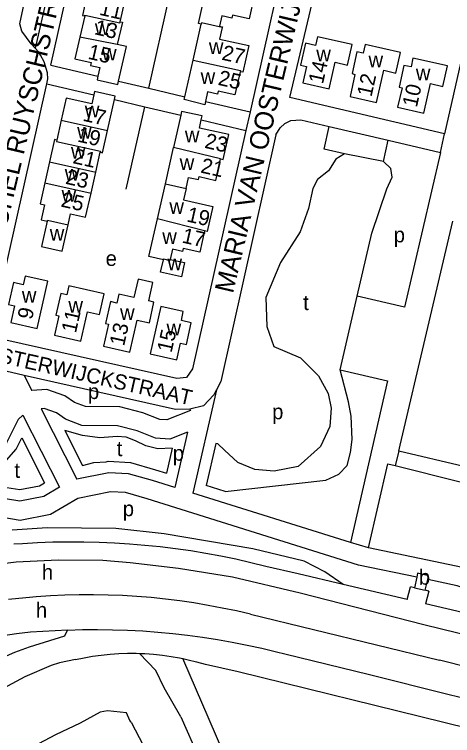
# Model space of a CAD drawing. Extents: x 161141 to 163125, y 381621 to 383200.
# Drawn here: x 162701.6 to 162817.4, y 382505.7 to 382696 of the extents above; entities that cross this region are included whole.
import ezdxf

# ---------------------------------------------------------------- set-up
doc = ezdxf.new("R2010")
doc.units = 0
for name, color, linetype in [('BLT_Basislijn', 7, 'Continuous'), ('BLT_Bebouwing', 7, 'Continuous'), ('BLT_Centroide', 7, 'Continuous'), ('BLT_Huisnummer', 7, 'Continuous'), ('BLT_Huisnummer_ tussenligend', 7, 'Continuous'), ('BLT_Onderverdeling_panden', 7, 'Continuous'), ('BLT_Straatnaam', 7, 'Continuous'), ('BLT_Straatnaam_verkleind', 7, 'Continuous'), ('BLT_Vlakafsluiter', 7, 'Continuous')]:
    doc.layers.add(name, color=color, linetype=linetype)

msp = doc.modelspace()

# ---------------------------------------------------------------- linework, layer by layer
at = {"layer": 'BLT_Basislijn'}
for p, q in [((162835.43, 382754.42), (162815.29, 382664.48)), ((162718.61, 382738.28), (162707.12, 382687.12)), ((162774.36, 382674.08), (162785.51, 382721.41)), ((162737.14, 382676.56), (162745.62, 382714.36)), ((162711.23, 382682.63), (162723.66, 382679.72)), ((162710.14, 382677.75), (162710.43, 382679.04)), ((162710.14, 382677.75), (162722.56, 382674.84)), ((162729.12, 382678.44), (162737.14, 382676.56)), ((162737.14, 382676.56), (162746.66, 382674.33)), ((162728.04, 382673.56), (162736.05, 382671.68)), ((162752.1, 382673.06), (162763.86, 382670.3)), ((162815.29, 382664.48), (162774.36, 382674.08)), ((162731.16, 382649.91), (162736.05, 382671.68)), ((162736.05, 382671.68), (162745.55, 382669.46)), ((162763.86, 382670.3), (162762.77, 382665.42)), ((162750.98, 382668.19), (162762.77, 382665.42)), ((162784.81, 382666.49), (162800.4, 382662.84)), ((162814.18, 382659.61), (162815.29, 382664.48)), ((162799.12, 382657.2), (162800.4, 382662.84)), ((162800.4, 382662.84), (162814.18, 382659.61)), ((162799.12, 382657.2), (162788.83, 382659.27)), ((162787.69, 382602.21), (162792.21, 382621.65)), ((162704.17, 382600.76), (162697.84, 382602.18)), ((162704.17, 382600.76), (162706.18, 382596.79)), ((162754.98, 382596.91), (162748.77, 382569.63)), ((162708.64, 382591.92), (162718.08, 382573.32)), ((162703.87, 382590.29), (162713.53, 382571.23)), ((162714.89, 382586.24), (162719.59, 382576.97)), ((162747.32, 382585.78), (162743.99, 382571.13)), ((162703.55, 382584.28), (162709.57, 382572.39)), ((162754.84, 382582.77), (162752.31, 382571.67)), ((162743.28, 382581.56), (162741.78, 382574.96)), ((162803.15, 382580.79), (162802.26, 382576.98)), ((162795.18, 382555.25), (162800.31, 382577.44)), ((162800.31, 382577.44), (162802.26, 382576.98)), ((162802.26, 382576.98), (162819.43, 382572.68)), ((162757.27, 382570.11), (162752.31, 382571.67)), ((162790.37, 382556.61), (162748.77, 382569.63)), ((162776.57, 382548.34), (162768.04, 382550.34)), ((162805.37, 382541.57), (162788.49, 382545.54)), ((162805.37, 382541.57), (162806.26, 382544.94)), ((162807.3, 382544.69), (162806.26, 382544.94)), ((162811.09, 382543.81), (162810.17, 382544.02)), ((162811.09, 382543.81), (162810.23, 382540.43)), ((162821.55, 382537.78), (162810.23, 382540.43)), ((162763.95, 382537.7), (162813.94, 382525.55)), ((162760.71, 382522.48), (162752.12, 382524.47)), ((162881.67, 382508.9), (162813.94, 382525.55)), ((162816.16, 382516.59), (162851.44, 382508)), ((162732.47, 382509.17), (162740.29, 382494.42))]:
    msp.add_line(p, q, dxfattribs=at)
for points in [[(162711.23, 382682.63), (162722.71, 382733.71), (162724.17, 382735.99), (162726.65, 382736.47)], [(162726.65, 382736.47), (162772.95, 382726.08), (162775.02, 382724.6), (162775.44, 382721.95), (162763.86, 382670.3)], [(162707.12, 382687.12), (162706.01, 382688.31), (162703.53, 382691.59), (162703.02, 382693.58), (162712.03, 382735.63)], [(162708.5, 382685.25), (162707.97, 382686.2), (162707.12, 382687.12)], [(162710.43, 382679.04), (162710.31, 382680.65), (162709.43, 382683.57), (162708.5, 382685.25)], [(162762.77, 382665.42), (162748.66, 382602.48), (162747.05, 382600.23), (162744.53, 382599.9), (162698.59, 382610.21), (162696.32, 382611.84), (162695.88, 382614.28), (162710.14, 382677.75)], [(162770.7, 382664.23), (162771.81, 382666.12), (162773.05, 382667.29), (162774.66, 382668.03), (162777.29, 382668.26), (162784.81, 382666.49)], [(162788.83, 382659.27), (162783.47, 382660.46), (162784.81, 382666.49)], [(162770.7, 382664.23), (162756.11, 382599.15), (162754.98, 382596.91)], [(162788.83, 382659.27), (162786.56, 382657.79), (162784.58, 382654.72), (162781.68, 382652.5), (162780.42, 382650.12), (162779.29, 382644.83), (162777.08, 382638.68), (162771.89, 382630.57), (162768.05, 382621.34), (162768.34, 382613.62), (162770.12, 382608.38), (162777.24, 382605.36), (162781.98, 382600.62), (162784.54, 382596.01), (162785.3, 382592.12), (162784.94, 382587.25), (162782.51, 382581.94), (162776.55, 382576.71), (162770.25, 382575.44), (162765.11, 382575.9), (162760.67, 382577.8), (162757.11, 382581.05), (162755.32, 382582.66), (162754.84, 382582.77)], [(162814.18, 382659.61), (162804.71, 382618.75), (162792.21, 382621.65)], [(162792.21, 382621.65), (162796.07, 382638.32), (162799.99, 382650.02), (162801.39, 382653.06), (162801.1, 382655.41), (162799.12, 382657.2)], [(162747.99, 382591.83), (162744.16, 382591.79), (162704.17, 382600.76)], [(162757.27, 382570.11), (162783.9, 382573.09), (162787.33, 382574.64), (162789.53, 382576.98), (162790.44, 382580.37), (162790.84, 382583.86), (162790.56, 382589.96), (162789.87, 382593.78), (162787.69, 382602.21)], [(162787.69, 382602.21), (162800.23, 382599.29), (162790.37, 382556.61)], [(162747.99, 382591.83), (162748.12, 382591.49), (162741.89, 382588.99), (162740, 382589.1), (162735.58, 382590.89), (162729.49, 382592.46), (162720.37, 382592.52), (162717.47, 382593.64), (162714.95, 382595.36), (162710.16, 382597.02), (162706.18, 382596.79)], [(162754.98, 382596.91), (162754.32, 382595.59), (162751.53, 382592.74), (162747.99, 382591.83)], [(162747.32, 382585.78), (162742.71, 382583.94), (162738.89, 382584.16), (162734.01, 382586.13), (162728.84, 382587.46), (162719.42, 382587.53), (162715.13, 382589.19), (162712.69, 382590.85), (162709.46, 382591.97), (162708.64, 382591.92)], [(162703.87, 382590.29), (162702.59, 382589.07), (162699.54, 382582.95), (162697.01, 382580.08), (162693.75, 382578.47), (162689.15, 382577.94), (162671.68, 382581.55), (162661.08, 382583.27), (162655, 382582), (162643.58, 382576.04), (162635.25, 382575.98)], [(162743.28, 382581.56), (162739.52, 382581.39), (162736.37, 382582.15), (162733.63, 382583.45), (162731.14, 382584.41), (162728.72, 382584.64), (162724.15, 382584.28), (162719.59, 382584.86), (162714.89, 382586.24)], [(162692.86, 382575.35), (162694.61, 382575.55), (162698.87, 382577.65), (162702.05, 382581.26), (162703.55, 382584.28)], [(162719.59, 382576.97), (162722.63, 382577.78), (162725.81, 382577.96)], [(162725.81, 382577.96), (162726.38, 382578.07), (162732.25, 382577.74), (162738.93, 382575.86), (162741.78, 382574.96)], [(162743.99, 382571.13), (162738.07, 382572.98), (162731.75, 382574.76), (162726.59, 382575.06), (162718.08, 382573.32)], [(162697.23, 382571.54), (162703.02, 382570.59), (162708.26, 382571.62), (162709.57, 382572.39)], [(162713.53, 382571.23), (162709.34, 382568.78), (162703.06, 382567.54), (162695.34, 382568.81), (162690.28, 382568.97), (162676.08, 382565.57), (162670.15, 382562.62), (162664.7, 382561.09), (162659.13, 382560.99), (162654.86, 382562.05), (162648.9, 382562.56), (162643.26, 382561.66)], [(162807.9, 382547.46), (162792.55, 382550.69), (162736.65, 382568.19), (162730.92, 382569.8), (162726.96, 382570.03), (162718.36, 382568.27), (162711.14, 382564.04), (162703.14, 382562.46), (162694.85, 382563.83), (162690.79, 382563.96), (162677.8, 382560.84), (162671.95, 382557.93), (162665.43, 382556.1), (162658.56, 382555.98), (162654.04, 382557.1), (162649.08, 382557.53), (162645.86, 382557.01)], [(162788.49, 382545.54), (162783.64, 382548.91), (162778.14, 382551.71), (162764.57, 382554.97), (162741.18, 382558.95), (162728.39, 382560.31), (162710.28, 382560.55), (162701.04, 382559.91)], [(162768.04, 382550.34), (162764.1, 382551.31), (162760.14, 382552.2), (162756.17, 382553.01), (162752.18, 382553.74), (162748.18, 382554.4), (162744.16, 382554.97), (162740.14, 382555.47), (162736.11, 382555.88), (162732.06, 382556.22), (162728.02, 382556.48), (162723.96, 382556.65), (162719.91, 382556.75), (162715.86, 382556.76), (162711.8, 382556.7), (162707.75, 382556.56), (162703.7, 382556.33), (162701.42, 382556.17)], [(162873.97, 382530.99), (162819.97, 382550.04), (162795.18, 382555.25)], [(162569.6, 382521.35), (162584.37, 382523.33), (162593.88, 382525.6), (162600, 382527.33), (162655.99, 382543.26), (162670.43, 382546.76), (162685.89, 382549.55), (162702.06, 382551.54), (162713.15, 382552.1), (162724.94, 382551.95), (162732.15, 382551.34), (162744.93, 382549.87), (162759.21, 382547.56), (162777.1, 382543.36)], [(162872.83, 382526.09), (162818.61, 382545.21), (162810.81, 382546.85)], [(162763.95, 382537.7), (162760.25, 382538.56), (162756.53, 382539.34), (162752.79, 382540.05), (162749.04, 382540.67), (162745.28, 382541.22), (162741.51, 382541.69), (162737.73, 382542.08), (162733.94, 382542.39), (162730.14, 382542.62), (162726.34, 382542.77), (162722.54, 382542.84), (162718.74, 382542.83), (162714.94, 382542.74), (162711.14, 382542.57), (162707.35, 382542.32), (162706.45, 382542.24), (162700.03, 382541.58)], [(162777.1, 382543.36), (162809.81, 382535), (162973.35, 382494.97)], [(162635.09, 382492.15), (162665.21, 382508.92), (162681.25, 382517.73), (162685.54, 382519.91), (162688.83, 382522.06), (162701.71, 382527.67), (162705.61, 382529.13), (162714.9, 382532), (162715.61, 382533.53)], [(162715.61, 382533.53), (162705.86, 382532.98), (162702.2, 382532.57), (162688.42, 382530.52), (162682.16, 382529.39), (162667.63, 382525.88), (162662.54, 382524.47), (162655.66, 382522.39), (162644.49, 382518.49)], [(162715.61, 382533.53), (162719.59, 382533.64), (162723.57, 382533.67), (162727.55, 382533.62), (162731.52, 382533.49), (162735.5, 382533.28), (162739.46, 382532.99), (162743.43, 382532.62), (162747.38, 382532.17), (162751.33, 382531.64), (162755.26, 382531.04), (162759.18, 382530.35), (162763.08, 382529.58), (162766.97, 382528.74), (162770.84, 382527.82), (162773.1, 382527.24)], [(162717.74, 382525.73), (162720, 382526.21), (162722.28, 382526.6), (162724.57, 382526.92), (162726.87, 382527.16), (162729.17, 382527.31), (162731.48, 382527.39), (162733.79, 382527.39), (162734.62, 382527.36)], [(162734.62, 382527.36), (162736.1, 382527.3), (162738.4, 382527.14), (162740.7, 382526.9), (162742.99, 382526.58), (162745.26, 382526.18), (162746.13, 382525.99)], [(162745.62, 382510.59), (162741.15, 382518.26), (162738.98, 382522.83), (162734.62, 382527.36)], [(162773.1, 382527.24), (162795.46, 382521.83), (162816.16, 382516.59)], [(162717.74, 382525.73), (162713.53, 382524.85), (162711.3, 382524.13), (162704.33, 382521.18), (162697.44, 382517.47), (162696.59, 382516.78), (162651.61, 382490.8), (162648.85, 382489.01), (162625.07, 382475.48), (162622.04, 382472.42), (162620.44, 382469.49), (162619.11, 382464.04), (162619.69, 382459.37), (162620.18, 382458.53)], [(162769.9, 382470.76), (162768.63, 382473.86), (162746.13, 382525.99)], [(162746.13, 382525.99), (162747.52, 382525.7), (162749.76, 382525.14), (162751.99, 382524.51), (162752.12, 382524.47)], [(162915.76, 382484.32), (162815.12, 382509.09), (162760.71, 382522.48)], [(162732.47, 382509.17), (162732.08, 382509.61), (162731.19, 382511.7), (162726.24, 382512.22), (162724.24, 382511.84), (162718.98, 382508.96), (162712.44, 382505.83), (162698.84, 382498.61), (162698.08, 382498.37), (162691.49, 382494.7), (162628.15, 382461.41), (162628.26, 382460.6), (162629.1, 382458.51), (162642.19, 382433.33), (162648.99, 382420.26)], [(162745.62, 382510.59), (162750.26, 382500.06), (162766.91, 382460.44)]]:
    msp.add_lwpolyline(points, dxfattribs=at)
at = {"layer": 'BLT_Bebouwing'}
for p, q in [((162729.54, 382694.1), (162730.76, 382699.43)), ((162720.17, 382695.66), (162718.91, 382690.07)), ((162748.83, 382684), (162750.95, 382693.49)), ((162746.66, 382674.33), (162748.83, 382684)), ((162726.19, 382665.38), (162728.04, 382673.56)), ((162745.55, 382669.46), (162743.64, 382660.95)), ((162713.98, 382668.11), (162712.81, 382662.88)), ((162723.1, 382654.39), (162724.29, 382659.67)), ((162741.49, 382651.36), (162743.64, 382660.95)), ((162710.9, 382657.12), (162709.66, 382651.55)), ((162721.85, 382648.82), (162723.1, 382654.39)), ((162739.4, 382642.05), (162741.49, 382651.36)), ((162710.26, 382641.5), (162708.77, 382634.76)), ((162803.52, 382582.36), (162817.43, 382641.46)), ((162820.39, 382576.73), (162803.15, 382580.79)), ((162807.9, 382547.46), (162807.3, 382544.69)), ((162810.17, 382544.02), (162810.81, 382546.85))]:
    msp.add_line(p, q, dxfattribs=at)
for points in [[(162750.95, 382693.49), (162750.21, 382693.66), (162752.62, 382704.34), (162754.89, 382703.54)], [(162720.94, 382701.88), (162719.58, 382695.79), (162720.17, 382695.66)], [(162764.99, 382700.99), (162763.61, 382694.85), (162759.21, 382695.83), (162759.04, 382695.04), (162756.4, 382695.63), (162755.8, 382692.93), (162756.58, 382692.76), (162756.53, 382692.56)], [(162729.54, 382694.1), (162730.13, 382693.97), (162728.79, 382688.11)], [(162756.53, 382692.56), (162755.84, 382689.53), (162763.57, 382687.82), (162761.99, 382680.77), (162761.26, 382680.93)], [(162718.91, 382690.07), (162717.61, 382684.29), (162721.86, 382683.34), (162721.68, 382682.56), (162724.17, 382682), (162723.66, 382679.72)], [(162729.12, 382678.44), (162731.19, 382687.56), (162728.79, 382688.11)], [(162761.26, 382680.93), (162759.86, 382674.79), (162755.48, 382675.78), (162755.3, 382675), (162752.67, 382675.59), (162752.1, 382673.06)], [(162723.66, 382679.72), (162723.45, 382678.77), (162728.92, 382677.53), (162729.12, 382678.44)], [(162728.04, 382673.56), (162728.24, 382674.46), (162722.75, 382675.68), (162722.56, 382674.84)], [(162722.56, 382674.84), (162722.03, 382672.48), (162715.3, 382673.98), (162713.98, 382668.11)], [(162752.1, 382673.06), (162751.9, 382672.18), (162746.5, 382673.6), (162746.66, 382674.33)], [(162750.98, 382668.19), (162751.23, 382669.29), (162745.78, 382670.46), (162745.55, 382669.46)], [(162756.09, 382657.9), (162756.81, 382657.72), (162758.29, 382664.31), (162750.51, 382666.05), (162750.98, 382668.19)], [(162724.29, 382659.67), (162724.87, 382659.54), (162726.19, 382665.38)], [(162712.81, 382662.88), (162712.22, 382662.99), (162710.9, 382657.12)], [(162746.96, 382650.1), (162747.62, 382653.03), (162750.24, 382652.44), (162750.42, 382653.22), (162754.81, 382652.24), (162756.09, 382657.9)], [(162709.66, 382651.55), (162708.43, 382646.07), (162709.58, 382645.81), (162708.69, 382641.86), (162710.26, 382641.5)], [(162715.81, 382640.49), (162716.47, 382643.44), (162720.43, 382642.55), (162721.85, 382648.82)], [(162746.96, 382650.1), (162746.28, 382647.13), (162754.05, 382645.37), (162752.56, 382638.78), (162751.84, 382638.95)], [(162740.99, 382631.23), (162737.16, 382632.1), (162739.4, 382642.05)], [(162708.77, 382634.76), (162714.24, 382633.53), (162715.81, 382640.49)], [(162751.84, 382638.95), (162750.56, 382633.29), (162746.16, 382634.26), (162745.99, 382633.49), (162743.35, 382634.09), (162742.74, 382631.39)], [(162742.74, 382631.39), (162746.56, 382630.53), (162745.72, 382626.78), (162740.25, 382628), (162740.99, 382631.23)], [(162738.48, 382620.11), (162737.1, 382620.42), (162738.19, 382625.29), (162734.29, 382626.17), (162733.2, 382621.29), (162729.17, 382622.19), (162728.65, 382619.86), (162727, 382620.22), (162725.7, 382614.47), (162726.48, 382614.28), (162725.18, 382608.44), (162732.13, 382606.88), (162734.04, 382615.37), (162737.32, 382614.63), (162738.48, 382620.11)], [(162803.15, 382580.79), (162803.52, 382582.36)], [(162810.81, 382546.85), (162811.04, 382547.88), (162808.13, 382548.55), (162807.9, 382547.46)], [(162807.3, 382544.69), (162810.17, 382544.02)]]:
    msp.add_lwpolyline(points, dxfattribs=at)
for points in [[(162781.69, 382690.17), (162781.17, 382687.84), (162778.55, 382688.42), (162777.24, 382682.69), (162778.8, 382682.33), (162777.81, 382677.95), (162784.78, 382676.38), (162786.4, 382683.41), (162789.62, 382682.67), (162790.84, 382688.12)], [(162803.6, 382686.03), (162794.29, 382688.11), (162793.77, 382685.8), (162792.12, 382686.16), (162790.84, 382680.41), (162791.6, 382680.22), (162790.3, 382674.37), (162797.26, 382672.8), (162799.18, 382681.29), (162802.38, 382680.56)], [(162804.54, 382682.59), (162803.23, 382676.86), (162804.03, 382676.68), (162802.87, 382671.57), (162809.83, 382670.01), (162811.59, 382677.77), (162814.79, 382677.04), (162816.01, 382682.46), (162806.92, 382684.5), (162806.41, 382682.18)], [(162710.43, 382625.63), (162704.48, 382626.98), (162703.96, 382624.66), (162701.34, 382625.24), (162700.07, 382619.47), (162701.63, 382619.12), (162700.64, 382614.73), (162707.61, 382613.17)], [(162725.35, 382622.28), (162716.02, 382624.38), (162715.49, 382622.04), (162713.85, 382622.41), (162712.55, 382616.66), (162713.33, 382616.48), (162712.22, 382611.35), (162719.16, 382609.8), (162720.89, 382617.51), (162724.12, 382616.83)], [(162746.24, 382617.6), (162740.34, 382618.91), (162737.52, 382606.44), (162744.49, 382604.87), (162745.48, 382609.25), (162747.04, 382608.91), (162748.33, 382614.63), (162745.72, 382615.26)]]:
    msp.add_lwpolyline(points, close=True, dxfattribs=at)
at = {"layer": 'BLT_Onderverdeling_panden'}
for p, q in [((162728.79, 382688.11), (162718.91, 382690.07)), ((162713.98, 382668.11), (162726.19, 382665.38)), ((162756.09, 382657.9), (162743.64, 382660.95)), ((162710.9, 382657.12), (162723.1, 382654.39)), ((162709.66, 382651.55), (162721.85, 382648.82)), ((162741.49, 382651.36), (162746.96, 382650.1)), ((162751.84, 382638.95), (162739.4, 382642.05))]:
    msp.add_line(p, q, dxfattribs=at)
for points in [[(162720.17, 382695.66), (162720.22, 382695.88), (162729.47, 382693.8), (162729.54, 382694.1)], [(162756.53, 382692.56), (162751.02, 382693.78), (162750.95, 382693.49)], [(162748.83, 382684), (162761.32, 382681.2), (162761.26, 382680.93)], [(162712.81, 382662.88), (162712.73, 382662.54), (162724.34, 382659.92), (162724.29, 382659.67)], [(162710.26, 382641.5), (162710.31, 382641.73), (162715.81, 382640.49)], [(162740.99, 382631.23), (162741.04, 382631.48), (162742.68, 382631.11), (162742.74, 382631.39)]]:
    msp.add_lwpolyline(points, dxfattribs=at)
at = {"layer": 'BLT_Vlakafsluiter'}
for p, q in [((162795.18, 382555.25), (162790.37, 382556.61)), ((162788.49, 382545.54), (162776.57, 382548.34))]:
    msp.add_line(p, q, dxfattribs=at)

# ---------------------------------------------------------------- texts
at = {"layer": 'BLT_Centroide'}
for s, p in [('w', (162722.87, 382690.62)), ('w', (162752.99, 382685.61)), ('w', (162724.76, 382683.88)), ('w', (162781.37, 382683.67)), ('w', (162795.17, 382682.08)), ('w', (162750.81, 382677.7)), ('w', (162807.68, 382678.67)), ('w', (162720.21, 382668.85)), ('w', (162718.18, 382663.27)), ('w', (162746.65, 382662.28)), ('w', (162716.55, 382657.98)), ('w', (162745.27, 382654.96)), ('w', (162714.92, 382652.14)), ('w', (162714.08, 382646.6)), ('w', (162742.55, 382643.39)), ('w', (162710.94, 382636.33)), ('p', (162801.83, 382635.88)), ('w', (162740.67, 382635.47)), ('e', (162725.71, 382629.65)), ('w', (162742.05, 382628.51)), ('w', (162703.57, 382619.96)), ('t', (162777.91, 382617.99)), ('w', (162715.86, 382617.28)), ('w', (162729.52, 382615.37)), ('w', (162741.81, 382611.31)), ('p', (162721.04, 382594.51)), ('p', (162769.71, 382589.17)), ('t', (162728.66, 382579.43)), ('p', (162743.45, 382578.24)), ('t', (162701.62, 382573.7)), ('p', (162730.24, 382563.58)), ('h', (162708.86, 382546.81)), ('b', (162808.47, 382545.51)), ('h', (162707.29, 382536.81))]:
    msp.add_text(s, height=4, dxfattribs=at).set_placement(p)
at = {"layer": 'BLT_Huisnummer'}
for s, rotation, p in [('13', 347.309, (162722.52, 382690.85)), ('15', 347.309, (162720.83, 382684.37)), ('14', 77.309, (162783.13, 382677.5)), ('25', 347.309, (162755.2, 382677.49)), ('12', 77.309, (162795.94, 382674.1)), ('10', 77.309, (162807.94, 382671.34)), ('17', 347.309, (162719.47, 382668.01)), ('21', 347.309, (162716.84, 382656.81)), ('21', 347.309, (162750.61, 382654.33)), ('25', 347.309, (162713.68, 382645.36)), ('17', 347.309, (162745.66, 382635.86)), ('9', 77.309, (162706.25, 382615.29)), ('11', 77.309, (162717.85, 382611.76)), ('13', 77.309, (162730.57, 382608.31)), ('15', 77.309, (162743.12, 382606.58))]:
    msp.add_text(s, height=4, rotation=rotation, dxfattribs=at).set_placement(p)
at = {"layer": 'BLT_Huisnummer_ tussenligend'}
for s, p in [('11', (162723.84, 382695.98)), ('27', (162756.2, 382684.12)), ('19', (162718.07, 382662.51)), ('23', (162751.66, 382660.86)), ('23', (162714.91, 382651.37)), ('19', (162746.93, 382641.42))]:
    msp.add_text(s, height=4, rotation=347.309, dxfattribs=at).set_placement(p)
at = {"layer": 'BLT_Straatnaam'}
for s, p in [('MARIA VAN OOSTERWIJCKSTRAAT', (162759.35, 382622.2)), ('RACHEL RUYSCHSTRAAT', (162697.35, 382630.58))]:
    msp.add_text(s, height=4.9999, rotation=76.6957, dxfattribs=at).set_placement(p)
at = {"layer": 'BLT_Straatnaam_verkleind'}
msp.add_text('OOSTERWIJCKSTRAAT', height=4, rotation=347.3466, dxfattribs=at).set_placement((162689.21, 382606.05))

doc.saveas('drawing.dxf')
